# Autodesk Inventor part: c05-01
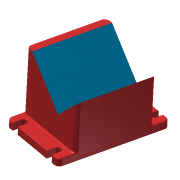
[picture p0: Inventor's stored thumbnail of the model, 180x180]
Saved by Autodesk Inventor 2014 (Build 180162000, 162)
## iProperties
Created: 2010-11
Part Number: c05-01
Material: Generic
Document SubType Name: Modeling
Designer: Thom Tremblay
Density: 1 g/cm^3
Appearance: Satin -Light Red
Author: Thom Tremblay
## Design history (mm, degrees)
sketch "Sketch1"
  geometry: L1 (-45, 0)-(45, 0); L2 (45, 0)-(45, 10); L3 (45, 10)-(-45, 10); L4 (-45, 10)-(-45, 0); L5 (-45, 10)-(-45, 90); L6 (-45, 90)-(-35, 90); L7 (-35, 90)-(14.497, 40.503); L8 (14.497, 40.503)-(45, 71.005); L9 (45, 71.005)-(45, 10); 2 further points
  constraints: 18 end point, 4 perpendicular, 3 collinear, 2 parallel, 2 point on line, 1 coincident, 1 horizontal, 1 midpoint
  dimensions: "d0" = 90 distance of L3.end L2.end; "d1" = 10 distance of L2.end L1.end; "d2" = 80 distance of L5.start L5.end; "d3" = 10 distance of L5.end L6.end; "d4" = 70 distance of L6.end L7.end; "d5" = 135 deg angle of L6 L7
extrude "Extrusion1" new body sketch "Sketch1" stored distance "d8" = 100; taper "d9" = 0 deg
extrude "Extrusion2" join sketch "Sketch1" stored distance "d10" = 140; taper "d11" = 0 deg
fillet "Fillet1" dims "d12" = 6
fillet "Fillet2" dims "d13" = 2
sketch "Sketch2"
  geometry: L1 (78, -2)-(0, -2) reference; L2 (-6, 4)-(-6, 132) reference; L3 (4.5, -2)-(13.5, -2); L4 (13.5, -2)-(13.5, 8); L5 (13.5, 8)-(4.5, 8); L6 (4.5, 8)-(4.5, -2); 2 further points
  constraints: 8 end point, 2 parallel, 1 horizontal, 1 horizontal alignment, 1 midpoint, 1 perpendicular, 1 point on line, 2 other
  dimensions: "d14" = 9 distance of L5.end L4.end; "d15" = 10 distance of L4.end L3.end; "d16" = 15 distance from line of point (9, 8) L2
extrude "Extrusion3" cut sketch "Sketch2" stored distance "d17" = 140; taper "d18" = 0 deg
mirror "Mirror1"
mirror "Mirror2"
body "Solid1"
